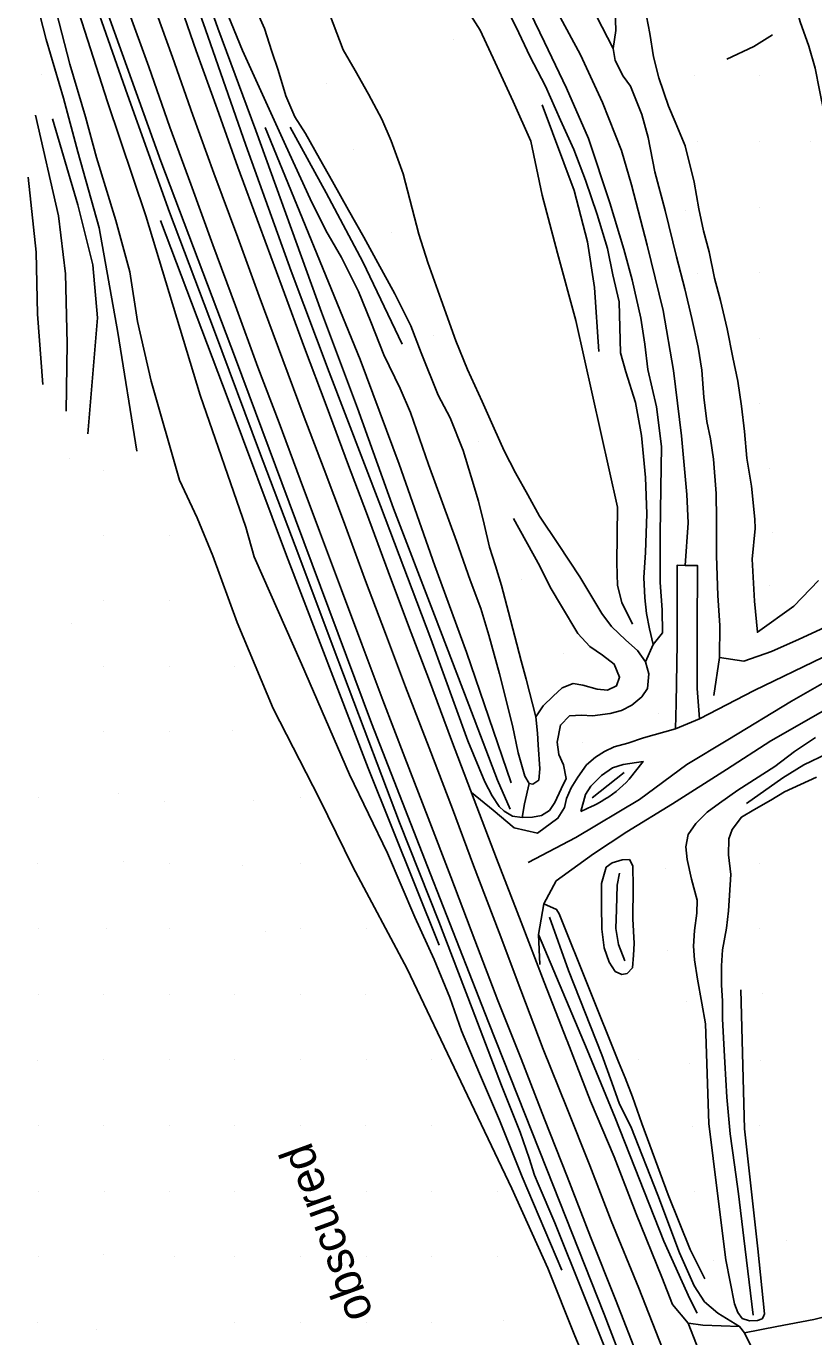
# Model space of a CAD drawing. Extents: x 524772 to 528246, y 273285 to 283088.
# Drawn here: x 527532.1 to 527649.1, y 274776.8 to 274971.6 of the extents above; entities that cross this region are included whole.
import ezdxf

# ---------------------------------------------------------------- set-up
doc = ezdxf.new("R2010")
doc.units = 0
for name, color, linetype in [('Exist DTM Crownline', 7, 'Continuous'), ('Exist Roads EOP', 7, 'Continuous'), ('Exist Roads EOP Other', 7, 'Continuous'), ('Exist Roads Soil', 7, 'Continuous'), ('Old_Level_12', 7, 'Continuous'), ('PH Exist DTM Breakline', 7, 'Continuous'), ('PH Exist DTM Point', 7, 'Continuous')]:
    doc.layers.add(name, color=color, linetype=linetype)

msp = doc.modelspace()

# ---------------------------------------------------------------- linework, layer by layer
at = {"layer": 'Exist DTM Crownline'}
msp.add_lwpolyline([(527626.66, 274775.03), (527623.13, 274784.01), (527619.03, 274794.02), (527615.84, 274802.22), (527612.42, 274810.78), (527608.89, 274819.5), (527605.6, 274828.29), (527602.37, 274836.88), (527598.57, 274846.82), (527595.42, 274855.27), (527591.94, 274864.31), (527588.43, 274873.38), (527585.45, 274881.31), (527582.51, 274889.14), (527579.23, 274898.08), (527576.33, 274905.68), (527573.21, 274913.88), (527570.23, 274921.97), (527566.68, 274931.46), (527563.52, 274940.17), (527559.95, 274949.75), (527556.85, 274958.38), (527553.79, 274966.98), (527550.64, 274975.81)], dxfattribs=at)
at = {"layer": 'Exist Roads EOP'}
for points in [[(527632.93, 274772.44), (527630.45, 274778.78), (527628.13, 274781.56), (527626.53, 274785.64), (527622.72, 274795.03), (527619.44, 274803.54), (527615.96, 274811.8), (527612.48, 274820.78), (527612.44, 274820.85), (527609.04, 274829.49), (527605.63, 274838.4), (527601.99, 274847.87), (527598.66, 274856.6), (527595.26, 274865.48), (527592, 274874.27), (527588.91, 274882.45), (527585.86, 274890.51), (527582.63, 274899.23), (527579.95, 274906.3), (527576.64, 274915.23), (527573.42, 274923.79), (527570.09, 274932.8), (527566.74, 274941.89), (527563.52, 274950.64), (527560.47, 274959.29), (527557.33, 274967.92), (527554.23, 274976.84)], [(527623.2, 274773.29), (527619.68, 274782.3), (527615.96, 274791.64), (527612.46, 274800.58), (527609.09, 274809.12), (527605.62, 274818.08), (527602.19, 274826.74), (527598.76, 274835.74), (527595.17, 274845.15), (527591.83, 274853.9), (527588.34, 274862.87), (527585.07, 274871.4), (527581.93, 274879.73), (527578.93, 274887.79), (527575.66, 274896.53), (527572.79, 274904.2), (527569.64, 274912.65), (527566.51, 274920.91), (527563.16, 274930.04), (527559.8, 274939.07), (527556.52, 274948.13), (527553.43, 274956.6), (527550.28, 274965.53), (527547.16, 274974.13)]]:
    msp.add_lwpolyline(points, dxfattribs=at)
at = {"layer": 'Exist Roads EOP Other'}
for points in [[(527630.52, 274778.81), (527630.45, 274778.78)], [(527630.52, 274778.81), (527632.66, 274778.52)]]:
    msp.add_lwpolyline(points, dxfattribs=at)
at = {"layer": 'Exist Roads Soil'}
for points in [[(527608.07, 274851.65), (527604.59, 274852.41), (527601.47, 274855.05), (527598.26, 274857.69)], [(527608.39, 274832.09), (527608.23, 274836.56), (527609.03, 274841.15), (527610.85, 274844.57)]]:
    msp.add_lwpolyline(points, dxfattribs=at)
at = {"layer": 'PH Exist DTM Breakline'}
for points in [[(527619.32, 274968.27), (527613.59, 274979.46), (527608.83, 274987.82), (527605.43, 274992.48), (527602.65, 274995.95), (527599.33, 275000.16), (527594.98, 275005.33), (527590.59, 275010.4)], [(527587.19, 275008.71), (527593.56, 275000.83), (527599.41, 274992.51), (527605.89, 274982.56), (527610.12, 274975.42), (527614.46, 274967.33), (527617.73, 274960.26), (527620.54, 274953.09), (527622.06, 274948.01), (527624.39, 274939.04), (527626.75, 274929.31), (527628.29, 274920.39), (527629.47, 274910.7), (527630.27, 274901.98), (527630.46, 274897.74), (527630.03, 274891.44)], [(527625.28, 274879.69), (527626.65, 274881.39), (527626.62, 274884.85), (527626.32, 274888.91), (527626.29, 274896.12), (527626.38, 274902.93), (527626.48, 274909.11), (527625.74, 274915.03), (527624.47, 274920.55), (527624.01, 274924.3), (527623.44, 274928.2), (527622.13, 274933.88), (527620.9, 274938.43), (527618.82, 274945.31), (527615.64, 274954.87), (527612.36, 274962.39), (527609.09, 274969.23), (527606.99, 274973.64), (527602.3, 274982.06), (527597.05, 274989.8), (527592.28, 274996.21), (527584.55, 275005.24)], [(527613.77, 274927.84), (527611.06, 274937.83), (527608.78, 274946.47), (527607.06, 274954.48), (527604.43, 274960.38), (527601.78, 274966.2), (527599.55, 274970.98), (527596.08, 274976.5), (527592.12, 274981.9), (527586.75, 274987.68), (527582.48, 274992.92)], [(527604.02, 274855.18), (527602.1, 274859.5), (527597.86, 274870.7), (527592.75, 274884.02), (527586.68, 274899.9), (527581.29, 274914.82), (527575.94, 274929.08), (527566.21, 274956.09), (527560.55, 274971.3), (527553.19, 274991.9)], [(527551.96, 274990.02), (527558.72, 274971.08), (527564.73, 274953.88), (527571.44, 274935.16), (527577.12, 274920.18), (527584.74, 274900.3), (527592.2, 274880.54), (527597.72, 274865.37), (527600.23, 274859.24), (527601.31, 274857.19), (527602.39, 274855.58), (527603.09, 274854.92), (527604.35, 274854.18), (527605.8, 274853.96), (527607.31, 274854.01), (527608.67, 274854.25), (527609.85, 274854.98), (527610.62, 274856.18), (527611.61, 274858.24), (527612.33, 274859.76), (527611.92, 274861.81), (527611.22, 274863.31), (527610.98, 274865.14), (527611.48, 274867.71), (527612.83, 274869.05), (527614.6, 274869.17), (527616.24, 274869.06), (527618.85, 274869.44), (527620.56, 274869.87), (527622.07, 274870.64), (527623.58, 274871.92), (527624.4, 274873.16), (527624.6, 274875.33), (527624.13, 274877.09), (527622.91, 274878.79), (527621.19, 274880.3), (527619.05, 274882.33), (527617.61, 274884.3), (527614.38, 274889.73), (527611.17, 274894.52), (527608.34, 274898.75), (527606.63, 274901.94), (527604.78, 274905.18), (527603.09, 274908.47), (527601.65, 274911.8), (527599.86, 274915.79), (527597.68, 274920.54), (527595.92, 274924.8), (527593.74, 274930.92), (527591.75, 274936.48), (527590.43, 274940.65), (527588.09, 274949.62), (527586.29, 274954.55), (527584.93, 274957.75), (527582.93, 274961.49), (527580.94, 274964.98), (527579.16, 274968.06), (527576.77, 274974.47)], [(527540.13, 274984.8), (527552.07, 274951.51), (527563.17, 274922.18), (527572.09, 274898.26), (527583.4, 274867.97), (527592.16, 274845.53), (527600.76, 274823.56), (527609.41, 274801.79), (527617.96, 274780.12), (527626.76, 274757.24), (527634.76, 274738.38)], [(527641.79, 274984.55), (527644.57, 274980), (527646.02, 274976.1), (527647.12, 274972.23), (527648.42, 274968.64), (527649.35, 274965.36), (527649.97, 274962.08), (527650.7, 274958.64), (527651.71, 274954.73), (527653.06, 274950.12), (527654.14, 274947.86)], [(527534.21, 274982.68), (527538.54, 274965.93), (527540.88, 274958.12), (527542.53, 274952.05), (527545.39, 274942.71), (527547.47, 274935.07), (527548.6, 274927.69), (527550.66, 274918.81), (527554.83, 274904.09), (527557.46, 274898.51), (527559.81, 274892.88), (527563.41, 274882.97), (527568.77, 274870.14), (527575.68, 274856.72), (527580.62, 274846.61), (527588.7, 274831.48), (527596.69, 274814.71), (527604.27, 274798.82), (527609.62, 274786.98), (527613.64, 274776.92), (527617.06, 274768.79), (527621.42, 274758.98), (527625.14, 274750.13), (527629.21, 274740.29)], [(527611.68, 274786.67), (527605.79, 274800.53), (527602.4, 274808.96), (527599.44, 274815.93), (527596.78, 274822.23), (527595.02, 274827.18), (527592.72, 274832.83), (527589.82, 274839.14), (527585.77, 274848.66), (527580.13, 274860.34), (527572.98, 274876.81), (527565.96, 274892.71), (527564.72, 274897.11), (527557.91, 274916.74), (527549.83, 274943.39), (527544.14, 274960.36), (527536.96, 274982.79)], [(527632.83, 274737.93), (527622.13, 274764.97), (527614.96, 274782.96), (527610.63, 274793.72), (527608.19, 274799.52), (527607.6, 274800.79), (527606.83, 274803.33), (527605.5, 274807.19), (527602.71, 274814.11), (527598.37, 274825.59), (527593.4, 274838.49), (527587.55, 274853.23), (527582.28, 274867.09), (527577.7, 274879.27), (527572.58, 274892.9), (527566.72, 274908.34), (527560.06, 274926.24), (527553.37, 274943.95), (527547.12, 274961.37), (527539.14, 274984.13)], [(527548.51, 274908.41), (527545.67, 274926.07), (527542.91, 274941.62), (527539.73, 274952.91), (527537.59, 274960.9), (527535.05, 274969.59), (527532.06, 274981.19)], [(527560.84, 274976.23), (527564.21, 274967.97), (527570.64, 274953.81), (527574.28, 274945.92), (527576.59, 274941.22), (527578.94, 274937.22), (527581.44, 274932.17), (527583.29, 274927.66), (527585.2, 274922.74), (527587.63, 274917.71), (527589.2, 274914.15), (527591.84, 274906.42), (527596.03, 274895.03), (527598.07, 274889.24), (527599.65, 274885.05), (527600.81, 274881.08), (527602.4, 274875.34), (527604.36, 274867.62), (527605.21, 274863.56), (527606.17, 274860.11), (527606.81, 274859.02), (527607.38, 274858.92), (527608.29, 274859.53), (527608.39, 274861.19), (527608.16, 274864.74), (527608.07, 274866.49), (527607.8, 274868.93)], [(527565.85, 274974.91), (527567.47, 274971.27), (527568.55, 274967.81), (527569.5, 274965.04), (527570.67, 274961.22), (527572, 274958.13), (527573.56, 274955.62), (527575.68, 274951.9), (527577.6, 274948.49), (527579.95, 274944.26), (527582.24, 274940.24), (527584.33, 274936.41), (527586.88, 274931.79), (527589.22, 274927.06), (527590.77, 274923.04), (527593.31, 274916.74), (527595.06, 274913.36), (527597.02, 274908.5), (527598.2, 274904.6), (527599.32, 274900.97), (527600.13, 274897.55), (527600.93, 274894.14), (527601.8, 274891.38), (527602.7, 274888.47), (527603.78, 274884.5), (527605.62, 274877.26), (527606.38, 274874.52), (527607.8, 274868.93), (527608.93, 274870.55), (527610.41, 274871.99), (527611.74, 274873.22), (527613.36, 274873.88), (527614.79, 274873.65), (527616.94, 274873.04), (527618.47, 274872.88), (527619.81, 274873.53), (527620.27, 274874.81), (527619.47, 274876.76), (527617.75, 274878.08), (527615.83, 274879.36), (527614.04, 274881.32), (527611.63, 274885.4), (527609.95, 274888.22), (527608.41, 274891.33), (527604.48, 274898.39)], [(527602.42, 274976.31), (527604.91, 274971.44), (527606.93, 274967.13), (527609.27, 274962.67), (527611.5, 274957.62), (527613.46, 274953.27), (527615.22, 274948.68), (527616.96, 274943.61), (527618.49, 274938.53), (527619.27, 274934.65), (527620.22, 274930.62), (527620.41, 274923.03), (527621.18, 274920.2), (527622.62, 274915.64), (527623.54, 274910.77), (527624.13, 274904.5), (527624.31, 274899.12), (527624.1, 274893.37), (527623.86, 274889.66), (527624.04, 274886.59), (527624.29, 274884.29), (527624.73, 274881.99), (527625.28, 274879.69), (527624.13, 274877.09)], [(527634.26, 274872.09), (527635.14, 274877.73), (527635.19, 274882.48), (527634.89, 274886.94), (527634.66, 274892.86), (527634.66, 274898.32), (527634.64, 274902.14), (527634.22, 274907.22), (527633.79, 274910.27), (527633.23, 274912.83), (527632.78, 274916.43), (527632.51, 274920.48), (527631.93, 274923.89), (527631, 274928.15), (527629.96, 274932.53), (527628.73, 274937.28), (527627.04, 274944.17), (527625.51, 274949.93), (527624.51, 274955.02), (527623.57, 274958.46), (527621.91, 274962.67), (527620.81, 274964.18), (527619.59, 274966.5), (527619.32, 274968.27), (527619.71, 274970.97), (527619.62, 274974.05)], [(527639.98, 274892.34), (527640.43, 274896.94), (527640.39, 274898.29), (527639.9, 274903.19), (527639.2, 274907.38), (527638.82, 274911.36), (527638.39, 274915.09), (527637.87, 274918.82), (527637.11, 274922.33), (527636.25, 274926.62), (527635.25, 274930.82), (527634.4, 274934.12), (527633.58, 274938.05), (527632.76, 274941.17), (527632.07, 274944.43), (527631.36, 274948.41), (527630, 274953.81), (527628.52, 274957.39), (527627.55, 274959.72), (527626.1, 274963.9), (527625.3, 274967.04), (527624.76, 274970.52), (527624.26, 274973.07)], [(527636.2, 274966.68), (527640.22, 274968.55), (527643, 274970.28)], [(527608.77, 274959.9), (527613.53, 274947.16), (527615.52, 274939.55), (527616.52, 274932.77), (527617.17, 274923.21)], [(527538, 274914.37), (527538.14, 274924.41), (527537.92, 274934.79), (527536.88, 274943.41), (527533.46, 274958.38)], [(527535.99, 274957.83), (527539.75, 274945.04), (527541.98, 274936.09), (527542.66, 274928.22), (527541.22, 274910.97)], [(527604.16, 274859.11), (527597.52, 274878.55), (527592.82, 274891.35), (527587.51, 274906.47), (527581.71, 274922.02), (527567.57, 274956.52)], [(527587.94, 274924.33), (527582.08, 274936.54), (527576.65, 274946.84), (527571.3, 274956.59)], [(527534.53, 274918.32), (527533.72, 274928.8), (527533.55, 274938.01), (527532.37, 274949.16)], [(527552.04, 274942.71), (527562.06, 274916.12), (527570.74, 274892.92), (527582.91, 274861.28), (527593.45, 274834.99)], [(527613.77, 274927.84), (527619.96, 274900.11), (527619.87, 274891.8), (527619.95, 274888.45), (527620.61, 274885.93), (527622.19, 274882.68)], [(527636.35, 274865.51), (527645.83, 274871.26), (527653.11, 274875.42), (527661.78, 274879.83), (527669.23, 274883.77), (527676.21, 274887.17), (527682.7, 274890.33), (527689.9, 274893.98), (527699.85, 274899.14), (527708.97, 274903.73), (527719.25, 274909.55), (527728.89, 274914.5), (527737.98, 274919.4), (527750.86, 274925.9)], [(527751.32, 274921.98), (527738.45, 274915.62), (527726.09, 274909.17), (527717.91, 274904.57), (527708.25, 274899.41), (527699.59, 274894.85), (527689.48, 274889.79), (527681.17, 274885.55), (527669.86, 274880.19), (527659.64, 274874.82), (527650.16, 274869.55), (527642.76, 274865.35), (527636.17, 274861.08), (527628.16, 274856.01), (527621.37, 274851.85), (527616.41, 274848.57), (527610.85, 274844.57)], [(527608.07, 274851.65), (527611.1, 274853.84), (527612.06, 274855.44), (527612.4, 274856.8), (527613.06, 274858.36), (527614.07, 274859.98), (527615.36, 274861.79), (527616.69, 274862.92), (527618.02, 274863.78), (527619.44, 274864.48), (527621.51, 274865.03), (527623.81, 274865.78), (527628.6, 274867.13), (527628.66, 274870.93), (527628.84, 274879.88), (527628.81, 274891.47), (527630.03, 274891.44), (527631.84, 274891.44), (527631.78, 274881.77), (527631.78, 274873.14), (527632.14, 274868.64), (527640.29, 274872.83), (527650.54, 274877.81)], [(527649.82, 274889.19), (527646.17, 274885.4), (527640.76, 274881.5), (527640.35, 274886.13), (527639.98, 274892.34)], [(527635.14, 274877.73), (527638.75, 274877.19), (527642.86, 274878.64), (527646.96, 274880.46), (527651.4, 274882.52)], [(527628.6, 274867.13), (527632.14, 274868.64)], [(527649.38, 274865.86), (527646.29, 274863.76), (527643.34, 274861.56), (527637.86, 274858.02), (527635.11, 274856.09), (527633.31, 274854.73), (527631.62, 274853.07), (527630.48, 274851.41), (527630.1, 274849.61), (527630.32, 274847.73), (527630.98, 274844.77), (527631.78, 274841.65), (527631.74, 274839.72), (527631.41, 274837.16), (527631.25, 274834.84), (527631.39, 274832.79), (527631.83, 274829.94), (527632.5, 274826.35), (527633.02, 274823.27)], [(527606.68, 274847.28), (527613.78, 274850.97), (527623.22, 274856.66), (527630.27, 274861.82), (527636.35, 274865.51)], [(527614.49, 274854.87), (527615.2, 274857.4), (527616.01, 274858.61), (527617.56, 274860.18), (527619.24, 274861.32), (527620.79, 274861.85), (527623.77, 274862.31), (527621.71, 274859.64), (527621.24, 274859.16), (527620.76, 274858.7), (527620.26, 274858.26), (527619.74, 274857.83), (527619.2, 274857.43), (527618.66, 274857.04), (527618.1, 274856.67), (527617.52, 274856.33), (527616.94, 274856), (527616.34, 274855.7), (527616.2, 274855.63), (527614.49, 274854.87)], [(527639.14, 274856.04), (527644.53, 274859.88), (527647.64, 274861.8), (527651.16, 274863.47)], [(527616.17, 274856.87), (527620.95, 274860.63)], [(527644.78, 274857.8), (527649.53, 274859.95)], [(527605.8, 274853.96), (527606.12, 274855.98), (527606.81, 274859.02)], [(527640.13, 274779.96), (527638.73, 274791.41), (527637.94, 274798.03), (527637.33, 274802.33), (527636.69, 274806.93), (527636.21, 274812.38), (527635.93, 274817.52), (527635.73, 274821.22), (527635.59, 274824.01), (527635.57, 274826.65), (527635.42, 274829.07), (527635.4, 274831.9), (527635.58, 274834.27), (527636.14, 274837.53), (527636.48, 274840.07), (527636.81, 274845.51), (527636.45, 274848.42), (527636.51, 274850.8), (527637, 274852.2), (527638.39, 274854.02), (527640.21, 274855.11), (527642.76, 274856.55), (527644.78, 274857.8)], [(527618.28, 274846.56), (527619.17, 274847.2), (527620.65, 274847.69), (527621.73, 274847.71), (527622.22, 274846.79), (527622.28, 274843.6), (527622.23, 274838.89), (527622.43, 274835.24), (527622.35, 274833.52), (527622.18, 274831.59), (527621.39, 274830.77), (527620.61, 274830.64), (527619.63, 274831.07), (527618.73, 274832.45), (527617.98, 274834.58), (527617.62, 274837.35), (527617.6, 274840.89), (527617.56, 274844.13), (527618.28, 274846.56)], [(527621.07, 274832.66), (527620.13, 274835.06), (527619.69, 274837.47), (527619.82, 274840.31), (527619.91, 274843.88), (527620.25, 274845.69)], [(527609.03, 274841.15), (527610.91, 274840.29), (527611.31, 274839.64), (527620.13, 274817.63), (527621.08, 274815.25), (527622.2, 274812.44), (527623.59, 274808.48), (527627.48, 274797.89), (527630.78, 274789.73), (527632.93, 274785.38)], [(527638.1, 274778.3), (527634.87, 274780.26), (527632.9, 274781.98), (527631.38, 274784.36), (527629.17, 274789.26), (527625.94, 274797.83), (527621.96, 274808.02), (527620.24, 274811.37), (527619.13, 274814.56), (527617.64, 274818.68), (527612.67, 274831.23), (527609.85, 274839.14)], [(527608.23, 274836.56), (527615.45, 274819.45), (527619.62, 274809.34), (527626.84, 274790.96), (527630.69, 274782.42), (527631.82, 274780.26)], [(527633.02, 274823.27), (527633.55, 274808.48), (527634.84, 274798.05), (527636.04, 274788.23), (527637.33, 274781.68), (527637.84, 274780.39), (527638.51, 274779.49), (527639.59, 274779.15), (527640.78, 274779.17), (527641.46, 274779.46), (527641.66, 274779.77), (527641.79, 274780.17), (527640.83, 274789.85), (527638.82, 274807.66), (527638.27, 274828.32)], [(527654.47, 274780.68), (527649.13, 274779.36), (527643.66, 274778.31), (527638.84, 274777.38)], [(527632.66, 274778.52), (527638.1, 274778.3), (527638.84, 274777.38), (527642.57, 274769.88), (527638.62, 274764.34)]]:
    msp.add_lwpolyline(points, dxfattribs=at)
at = {"layer": 'PH Exist DTM Point'}
for p, q in [((527595.53, 274969.58), (527595.53, 274969.58)), ((527534.28, 274964.36), (527534.28, 274964.36)), ((527576.76, 274963.1), (527576.76, 274963.1)), ((527631.36, 274964.22), (527631.36, 274964.22)), ((527641.11, 274964.22), (527641.11, 274964.22)), ((527631.84, 274954.4), (527631.84, 274954.4)), ((527641.11, 274954.47), (527641.11, 274954.47)), ((527648.58, 274954.5), (527648.58, 274954.5)), ((527580.68, 274953.19), (527580.68, 274953.19)), ((527630.1, 274944.17), (527630.1, 274944.17)), ((527641.11, 274944.71), (527641.11, 274944.71)), ((527586.4, 274940.9), (527586.4, 274940.9)), ((527631.82, 274934.89), (527631.82, 274934.89)), ((527641.11, 274934.96), (527641.11, 274934.96)), ((527592.54, 274925.66), (527592.54, 274925.66)), ((527641.11, 274925.21), (527641.11, 274925.21)), ((527641.09, 274915.47), (527641.09, 274915.47)), ((527599.3, 274909.87), (527599.3, 274909.87)), ((527538.51, 274907.32), (527538.51, 274907.32)), ((527543.58, 274905.56), (527543.58, 274905.56)), ((527642.52, 274905.9), (527642.52, 274905.9)), ((527543.58, 274895.95), (527543.58, 274895.95)), ((527553.34, 274895.93), (527553.34, 274895.93)), ((527642.99, 274896.37), (527642.99, 274896.37)), ((527605.62, 274889.27), (527605.62, 274889.27)), ((527642.62, 274888.47), (527642.62, 274888.47)), ((527543.58, 274886.19), (527543.58, 274886.19)), ((527553.31, 274886.19), (527553.31, 274886.19)), ((527538.82, 274882.8), (527538.82, 274882.8)), ((527611.86, 274878.3), (527611.86, 274878.3)), ((527543.58, 274876.44), (527543.58, 274876.44)), ((527553.35, 274876.46), (527553.35, 274876.46)), ((527563.09, 274876.44), (527563.09, 274876.44)), ((527625.99, 274869.43), (527625.99, 274869.43)), ((527543.58, 274866.69), (527543.58, 274866.69)), ((527553.33, 274866.69), (527553.33, 274866.69)), ((527562.67, 274866.83), (527562.67, 274866.83)), ((527614.82, 274865.06), (527614.82, 274865.06)), ((527533.85, 274856.92), (527533.85, 274856.92)), ((527545.81, 274857.52), (527545.81, 274857.52)), ((527552.62, 274856.39), (527552.62, 274856.39)), ((527565.86, 274856.48), (527565.86, 274856.48)), ((527572.8, 274856.92), (527572.8, 274856.92)), ((527533.8, 274847.19), (527533.8, 274847.19)), ((527546.54, 274847.49), (527546.54, 274847.49)), ((527553.33, 274847.18), (527553.33, 274847.18)), ((527564.27, 274846.83), (527564.27, 274846.83)), ((527572.84, 274847.18), (527572.84, 274847.18)), ((527627.15, 274846.41), (527627.15, 274846.41)), ((527641.11, 274847.18), (527641.11, 274847.18)), ((527533.82, 274837.42), (527533.82, 274837.42)), ((527544.05, 274837.52), (527544.05, 274837.52)), ((527553.33, 274837.42), (527553.33, 274837.42)), ((527567.67, 274837.02), (527567.67, 274837.02)), ((527572.84, 274837.42), (527572.84, 274837.42)), ((527582.59, 274837.42), (527582.59, 274837.42)), ((527641.11, 274837.42), (527641.11, 274837.42)), ((527627.35, 274834.19), (527627.35, 274834.19)), ((527533.82, 274827.67), (527533.82, 274827.67)), ((527543.55, 274827.68), (527543.55, 274827.68)), ((527553.33, 274827.67), (527553.33, 274827.67)), ((527563.04, 274827.68), (527563.04, 274827.68)), ((527572.84, 274827.67), (527572.84, 274827.67)), ((527582.57, 274827.67), (527582.57, 274827.67)), ((527641.53, 274827.8), (527641.53, 274827.8)), ((527630.29, 274826.6), (527630.29, 274826.6)), ((527533.81, 274817.91), (527533.81, 274817.91)), ((527543.58, 274817.92), (527543.58, 274817.92)), ((527553.33, 274817.92), (527553.33, 274817.92)), ((527563.09, 274817.92), (527563.09, 274817.92)), ((527572.84, 274817.92), (527572.84, 274817.92)), ((527582.61, 274817.92), (527582.61, 274817.92)), ((527592.35, 274817.92), (527592.35, 274817.92)), ((527623.12, 274818.02), (527623.12, 274818.02)), ((527630.62, 274817.34), (527630.62, 274817.34)), ((527641.27, 274817.9), (527641.27, 274817.9)), ((527533.84, 274808.17), (527533.84, 274808.17)), ((527543.58, 274808.16), (527543.58, 274808.16)), ((527553.33, 274808.16), (527553.33, 274808.16)), ((527563.09, 274808.16), (527563.09, 274808.16)), ((527572.84, 274808.16), (527572.84, 274808.16)), ((527582.57, 274808.16), (527582.57, 274808.16)), ((527592.35, 274808.16), (527592.35, 274808.16)), ((527631.18, 274808), (527631.18, 274808)), ((527641.11, 274808.16), (527641.11, 274808.16)), ((527533.82, 274798.41), (527533.82, 274798.41)), ((527543.7, 274798.43), (527543.7, 274798.43)), ((527553.33, 274798.41), (527553.33, 274798.41)), ((527563.09, 274798.41), (527563.09, 274798.41)), ((527572.84, 274798.41), (527572.84, 274798.41)), ((527582.59, 274798.41), (527582.59, 274798.41)), ((527592.35, 274798.41), (527592.35, 274798.41)), ((527602.1, 274798.41), (527602.1, 274798.41)), ((527631.34, 274798.42), (527631.34, 274798.42)), ((527645.12, 274791.02), (527645.12, 274791.02)), ((527533.82, 274788.66), (527533.82, 274788.66)), ((527543.56, 274789.07), (527543.56, 274789.07)), ((527554.04, 274788.71), (527554.04, 274788.71)), ((527563.09, 274788.66), (527563.09, 274788.66)), ((527572.84, 274788.66), (527572.84, 274788.66)), ((527582.59, 274788.66), (527582.59, 274788.66)), ((527592.35, 274788.66), (527592.35, 274788.66)), ((527602.1, 274788.66), (527602.1, 274788.66)), ((527634.21, 274788.11), (527634.21, 274788.11)), ((527533.81, 274778.9), (527533.81, 274778.9)), ((527563.09, 274778.9), (527563.09, 274778.9)), ((527572.84, 274778.9), (527572.84, 274778.9)), ((527582.59, 274778.9), (527582.59, 274778.9)), ((527592.35, 274778.9), (527592.35, 274778.9)), ((527603.01, 274779.14), (527603.01, 274779.14)), ((527542.46, 274777.8), (527542.46, 274777.8))]:
    msp.add_line(p, q, dxfattribs=at)

# ---------------------------------------------------------------- texts
at = {"layer": 'Old_Level_12'}
msp.add_text('obscured', height=5, rotation=110, dxfattribs=at).set_placement((527583.71, 274780.1))

doc.saveas('drawing.dxf')
